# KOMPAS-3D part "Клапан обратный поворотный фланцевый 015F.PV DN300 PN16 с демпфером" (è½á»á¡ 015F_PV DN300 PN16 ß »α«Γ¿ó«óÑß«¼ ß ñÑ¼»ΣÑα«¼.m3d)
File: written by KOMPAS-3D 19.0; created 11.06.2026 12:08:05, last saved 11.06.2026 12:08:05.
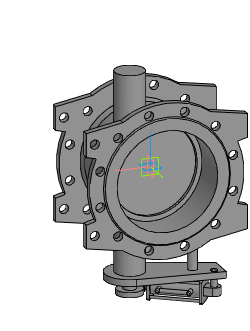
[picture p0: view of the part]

Document properties: Автор: Энергия; Полное имя файла: Z:\3.Личные\kachalov\001_3d для проектировщиков\5.5 Тип 015F.PV Клапан обратный поворотный с двумя эксцентриками\_stp_Клапан 015F.PV DN300-DN1200 с противовесом с демпфером\Клапан 015F_PV DN300 PN16 с противовесом с демпфером.m3d

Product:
- Part/product: Клапан обратный поворотный фланцевый 015F.PV DN300 PN16 с демпфером

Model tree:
1. Операция без истории:1
2. Сплайн:1
     Координата Y = 30; Координата Z = 150; Вес = 1; Координата X = 300; Координата Y = 69.4957; Координата Z = 150; Вес = 0.333333; Координата X = 300; Координата Y = 69.4957; Координата Z = -150; Вес = 0.333333; Координата Y = 30; Координата Z = -150; Вес = 1; Координата X = -300; Координата Y = -9.49575; Координата Z = -150; Вес = 0.333333; Координата X = -300; Координата Y = -9.49575; Координата Z = 150; Вес = 0.333333; Порядок = 4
